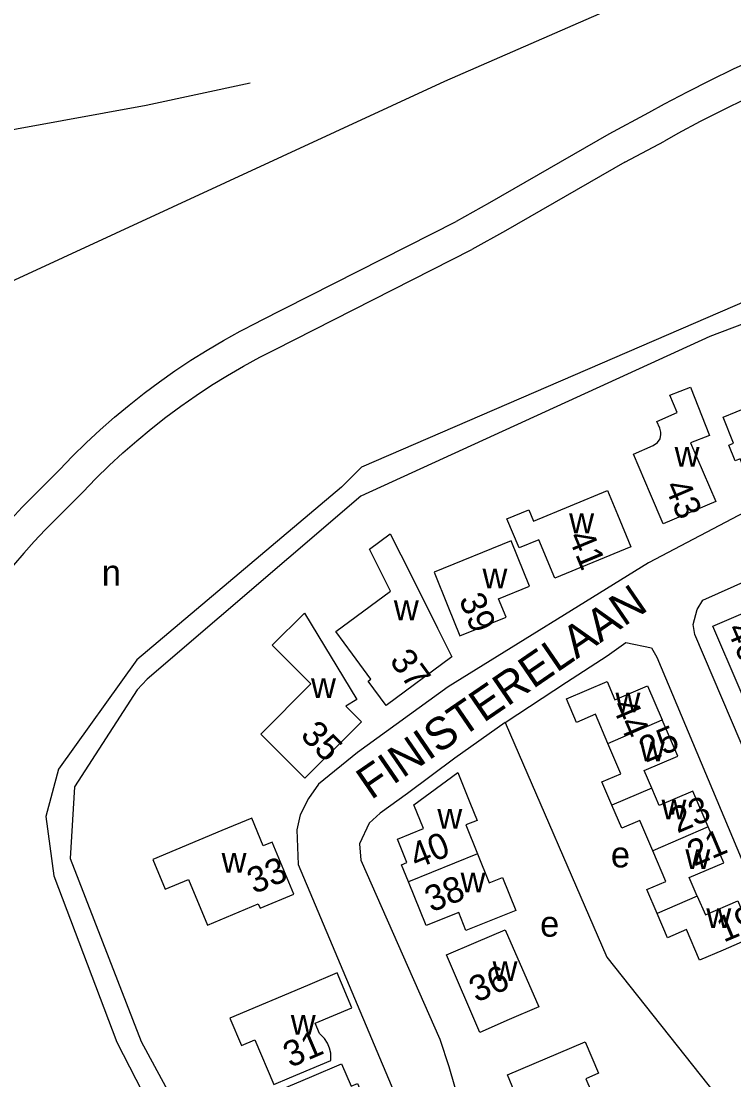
# Model space of a CAD drawing. Extents: x 157768 to 159790, y 387230 to 389604.
# Drawn here: x 158494.9 to 158605.5, y 389072.5 to 389236.8 of the extents above; entities that cross this region are included whole.
import ezdxf

# ---------------------------------------------------------------- set-up
doc = ezdxf.new("R2010")
doc.units = 0
for name, color, linetype in [('BLT_Basislijn', 7, 'Continuous'), ('BLT_Bebouwing', 7, 'Continuous'), ('BLT_Centroide', 7, 'Continuous'), ('BLT_Huisnummer', 7, 'Continuous'), ('BLT_Huisnummer_ tussenligend', 7, 'Continuous'), ('BLT_Onderverdeling_panden', 7, 'Continuous'), ('BLT_Straatnaam', 7, 'Continuous')]:
    doc.layers.add(name, color=color, linetype=linetype)

msp = doc.modelspace()

# ---------------------------------------------------------------- linework, layer by layer
at = {"layer": 'BLT_Basislijn'}
for p, q in [((158592.29, 389222.55), (158586.1, 389219.25)), ((158588.59, 389214.92), (158594.74, 389218.19)), ((158532.02, 389190.28), (158562.46, 389205.73)), ((158534.24, 389185.8), (158564.89, 389201.36)), ((158495.12, 389161.36), (158500.87, 389167.15)), ((158498.66, 389157.84), (158504.5, 389163.72)), ((158509.79, 389078.38), (158523.9, 389050.85))]:
    msp.add_line(p, q, dxfattribs=at)
for points in [[(158651.16, 389267), (158560.63, 389227.45), (158484.33, 389192.23)], [(158620.19, 389235.55), (158616.45, 389234.11), (158612.75, 389232.59), (158609.08, 389230.99), (158605.44, 389229.33), (158601.83, 389227.59), (158598.26, 389225.78), (158594.73, 389223.9), (158592.29, 389222.55)], [(158621.95, 389230.87), (158618.26, 389229.44), (158614.6, 389227.94), (158610.98, 389226.36), (158607.38, 389224.72), (158603.82, 389223), (158600.3, 389221.2), (158596.81, 389219.34), (158594.74, 389218.19)], [(158159.05, 389074.39), (158176.93, 389087.48), (158220.35, 389119.97), (158269.48, 389154.36), (158312.93, 389181.96), (158334.34, 389194.06), (158344.44, 389198.04), (158364.01, 389204.01), (158376.74, 389206.47), (158394.9, 389208.62), (158440.87, 389212.26), (158481.13, 389217.72), (158514.35, 389223.75), (158530.49, 389227.21)], [(158586.1, 389219.25), (158567.61, 389208.61), (158562.46, 389205.73)], [(158588.59, 389214.92), (158570.08, 389204.26), (158564.89, 389201.36)], [(158638.46, 389206.81), (158547.74, 389167.61), (158544.64, 389164.5)], [(158631.85, 389199.23), (158601.81, 389187.85), (158547.63, 389163.08), (158514.51, 389134.71), (158512.92, 389133.02), (158503.21, 389117.99), (158502.57, 389106.88), (158513.55, 389078.5), (158526.29, 389054.94), (158530.22, 389027.48), (158534.69, 389023.17)], [(158500.87, 389167.15), (158502.92, 389169.28), (158505.03, 389171.36), (158507.2, 389173.37), (158509.42, 389175.33), (158511.7, 389177.22), (158514.02, 389179.06), (158516.39, 389180.83), (158518.81, 389182.53), (158521.27, 389184.17), (158523.78, 389185.74), (158526.33, 389187.24), (158528.92, 389188.68), (158531.55, 389190.04), (158532.02, 389190.28)], [(158504.5, 389163.72), (158506.52, 389165.81), (158508.59, 389167.83), (158510.71, 389169.8), (158512.88, 389171.7), (158515.1, 389173.55), (158517.38, 389175.33), (158519.71, 389177.05), (158522.08, 389178.71), (158524.49, 389180.29), (158526.95, 389181.81), (158529.45, 389183.27), (158531.99, 389184.65), (158534.24, 389185.8)], [(158642.21, 389173.46), (158620.23, 389166.55), (158608.23, 389161.14), (158592.3, 389152.76), (158561.19, 389133.52), (158547.15, 389123.34), (158541.1, 389118.4), (158539.51, 389116.18), (158538.23, 389113.63), (158537.74, 389111.33), (158537.91, 389105.95), (158555.4, 389064.46), (158559.68, 389038.08), (158559.64, 389036.09), (158558.78, 389035.34), (158557.73, 389034.76)], [(158544.64, 389164.5), (158512.89, 389137.68), (158500.76, 389120.73), (158498.78, 389113.39), (158500, 389104.19), (158509.79, 389078.38)], [(158609.36, 389118.47), (158599.47, 389141.65), (158599.21, 389143.2), (158599.85, 389145.53), (158600.71, 389146.93), (158631.38, 389160.66), (158643.06, 389163.73), (158643.45, 389163.62), (158648.16, 389157.69), (158654.3, 389147.9)], [(158495.12, 389161.36), (158493.37, 389159.54), (158491.68, 389157.66), (158490.05, 389155.74), (158488.48, 389153.76), (158486.98, 389151.73), (158485.54, 389149.66), (158484.17, 389147.55), (158482.86, 389145.39), (158481.62, 389143.19), (158480.46, 389140.95), (158479.37, 389138.68), (158478.35, 389136.37), (158477.4, 389134.03), (158476.53, 389131.66), (158475.73, 389129.27), (158475.01, 389126.85), (158474.6, 389125.35)], [(158498.66, 389157.84), (158496.97, 389156.07), (158495.34, 389154.26), (158493.77, 389152.39), (158492.26, 389150.47), (158490.81, 389148.5), (158489.43, 389146.49), (158488.12, 389144.43), (158486.87, 389142.33), (158485.69, 389140.19), (158484.59, 389138.01), (158483.55, 389135.8), (158482.59, 389133.55), (158481.7, 389131.28), (158480.89, 389128.98), (158480.15, 389126.65), (158479.49, 389124.3), (158479.44, 389124.11)], [(158570.02, 389127.98), (158579.58, 389134.24), (158585.87, 389138.34), (158588.77, 389140.4), (158592.76, 389139.54), (158593.57, 389138.13), (158611.51, 389095.31), (158612.04, 389093.78)], [(158570.02, 389127.98), (158562.24, 389122.42), (158554.86, 389116.94), (158550.63, 389113.9), (158548.96, 389112.37), (158547.42, 389109.17), (158547.63, 389106.59), (158559.89, 389078.82), (158561.31, 389074.61), (158562.94, 389068.86), (158565.77, 389055.24), (158570.4, 389029.3), (158572.46, 389027.24), (158574.79, 389027.4), (158586.52, 389032.48), (158587.26, 389032.8)], [(158570.02, 389127.98), (158585.83, 389091.57), (158602.65, 389070.31)]]:
    msp.add_lwpolyline(points, dxfattribs=at)
at = {"layer": 'BLT_Bebouwing'}
for points in [[(158598.79, 389180), (158601.72, 389172.52), (158598.81, 389171.38), (158602.7, 389162.25), (158594.55, 389158.78), (158592.59, 389163.38), (158589.93, 389169.62)], [(158589.93, 389169.62), (158592.99, 389170.93), (158593.69, 389171.4), (158594.11, 389172.01), (158594.19, 389172.66), (158594.21, 389173.01), (158594.06, 389173.66), (158593.59, 389174.7), (158596.75, 389176.05), (158595.6, 389178.74), (158598.79, 389180)], [(158618.31, 389169.09), (158615.15, 389167.81), (158613.63, 389171.55), (158612.23, 389170.98), (158613.34, 389168.23), (158607.69, 389165.93), (158606.49, 389168.87), (158605.73, 389168.56), (158604.75, 389170.98), (158605.49, 389171.29), (158603.84, 389175.34), (158613.97, 389179.46), (158614.06, 389179.23)], [(158587.49, 389160.22), (158589.56, 389155.23), (158577.75, 389150.35), (158575.28, 389156.32), (158572.2, 389155.05), (158570.32, 389159.58), (158573.7, 389160.99), (158574.43, 389159.21), (158585.94, 389163.97), (158587.49, 389160.22)], [(158552.26, 389148.34), (158548.99, 389154.87), (158552.22, 389157.24), (158555.49, 389150.71)], [(158571.93, 389153.73), (158570.96, 389156.14), (158559, 389151.3), (158561.13, 389146.04), (158563.01, 389141.4), (158570.17, 389144.29), (158569.01, 389147.16), (158573.81, 389149.1), (158571.93, 389153.73)], [(158555.49, 389150.71), (158559.54, 389142.61)], [(158559.54, 389142.61), (158561.78, 389138.14), (158551.55, 389130.62), (158548.8, 389134.37), (158549.21, 389134.67), (158546.33, 389138.58), (158543.76, 389142.09), (158552.26, 389148.34)], [(158607.53, 389130.59), (158606.33, 389133.39), (158602.27, 389142.92), (158609.14, 389145.85)], [(158545.33, 389130.49), (158547.74, 389128.06), (158538.95, 389119.31), (158535.42, 389122.86), (158532.11, 389126.18), (158539.91, 389133.95), (158533.91, 389139.97), (158538.91, 389144.94), (158547.05, 389131.54), (158545.33, 389130.49)], [(158585.98, 389124.73), (158584.04, 389129.26), (158581.1, 389127.99), (158579.54, 389131.63), (158585.84, 389134.34), (158587.06, 389131.49), (158592.12, 389133.67), (158594.41, 389128.36)], [(158592.77, 389117.8), (158591.61, 389120.51), (158596.82, 389122.75), (158594.41, 389128.36)], [(158586.6, 389115.15), (158585.05, 389118.76), (158588, 389120.03), (158585.98, 389124.73)], [(158555.05, 389103.27), (158553.98, 389105.91), (158554.78, 389106.24), (158553.31, 389109.89), (158557.35, 389111.52), (158555.85, 389115.22), (158562.67, 389120.2), (158564.54, 389115.56), (158565.67, 389112.77), (158563.93, 389112.07), (158565.74, 389107.59)], [(158601.56, 389111.76), (158599.16, 389117.34), (158593.93, 389115.09), (158592.77, 389117.8)], [(158592.93, 389108.05), (158590.92, 389112.74), (158588.15, 389111.55), (158586.6, 389115.15)], [(158532.03, 389099.14), (158537.26, 389101.33), (158533.87, 389109.42), (158532.5, 389108.85), (158530.71, 389113.14), (158526.1, 389111.21), (158515.37, 389106.72), (158517.29, 389102.11), (158520.89, 389103.62), (158523.86, 389096.53), (158531.74, 389099.83), (158532.03, 389099.14)], [(158599.85, 389101.01), (158598.61, 389103.9), (158603.95, 389106.19), (158601.56, 389111.76)], [(158565.74, 389107.59), (158567.55, 389103.11), (158569.61, 389103.94), (158571.68, 389098.81), (158568.6, 389097.57), (158563.96, 389095.69), (158562.83, 389098.48), (158557.8, 389096.45), (158555.05, 389103.27)], [(158593.63, 389098.34), (158592.04, 389102.04), (158594.97, 389103.3), (158592.93, 389108.05)], [(158599.85, 389101.01), (158601.1, 389098.12), (158606.14, 389100.28), (158608.47, 389094.65), (158603.88, 389092.67), (158600.2, 389091.09), (158598.16, 389095.84), (158595.25, 389094.58), (158593.63, 389098.34)], [(158570.68, 389081.87), (158566.09, 389079.87), (158560.92, 389091.93), (158565.52, 389093.89), (158570.06, 389095.82), (158575.27, 389083.87), (158570.68, 389081.87)], [(158539.36, 389087.17), (158527.34, 389082.1), (158529.12, 389077.87), (158531.21, 389078.75), (158534.14, 389071.81), (158536.57, 389072.83), (158543.01, 389075.55), (158542.98, 389076.65), (158542.79, 389077.46), (158542.47, 389078.21), (158542.02, 389078.92), (158541.25, 389079.73), (158540.58, 389081.32), (158546.24, 389083.71), (158543.97, 389089.11), (158539.36, 389087.17)], [(158542.5, 389062.29), (158540.7, 389066.49), (158537.48, 389065.11), (158535, 389070.9), (158540.05, 389073.06), (158544.64, 389075.03), (158546.13, 389071.55), (158547.13, 389071.97), (158549.92, 389065.46)]]:
    msp.add_lwpolyline(points, dxfattribs=at)
msp.add_lwpolyline([(158570.4, 389073.32), (158582.45, 389078.41), (158584.53, 389073.54), (158582.55, 389072.69), (158583.38, 389070.76), (158578.17, 389068.54), (158580.12, 389063.99), (158571.55, 389060.33), (158568.13, 389068.24), (158571.86, 389069.81)], close=True, dxfattribs=at)
at = {"layer": 'BLT_Onderverdeling_panden'}
for p, q in [((158585.98, 389124.73), (158594.41, 389128.36)), ((158592.77, 389117.8), (158586.6, 389115.15)), ((158601.56, 389111.76), (158592.93, 389108.05)), ((158565.74, 389107.59), (158555.05, 389103.27)), ((158599.85, 389101.01), (158593.63, 389098.34))]:
    msp.add_line(p, q, dxfattribs=at)

# ---------------------------------------------------------------- texts
at = {"layer": 'BLT_Centroide'}
for s, p in [('w', (158596.33, 389167.66)), ('w', (158579.97, 389157.34)), ('n', (158507.45, 389149.22)), ('w', (158566.52, 389148.78)), ('w', (158552.77, 389143.83)), ('w', (158539.92, 389131.77)), ('w', (158587.16, 389129.53)), ('w', (158590.94, 389121.94)), ('w', (158594.3, 389112.94)), ('w', (158559.52, 389111.5)), ('e', (158586.44, 389105.49)), ('w', (158598, 389105.22)), ('w', (158526.04, 389104.66)), ('w', (158563.12, 389101.62)), ('w', (158601.25, 389096.06)), ('e', (158575.46, 389094.74)), ('w', (158568.09, 389087.86)), ('w', (158536.78, 389079.52))]:
    msp.add_text(s, height=4, dxfattribs=at).set_placement(p)
at = {"layer": 'BLT_Huisnummer'}
for s, rotation, p in [('43', 293.0888, (158594.7, 389164.66)), ('41', 292.5035, (158579.73, 389156.82)), ('39', 291.9993, (158562.81, 389147.11)), ('46', 293.0932, (158604.35, 389142.53)), ('37', 306.3128, (158551.98, 389137.53)), ('44', 293.2577, (158586.52, 389130.65)), ('35', 314.8542, (158538.11, 389125.84)), ('25', 22.8346, (158591.87, 389121.7)), ('40', 21.9934, (158556.26, 389105.21)), ('33', 22.7199, (158531.07, 389101.31)), ('38', 21.995, (158558.59, 389098.47)), ('19', 22.8346, (158603.94, 389093.8)), ('36', 23.5612, (158565.56, 389084.47)), ('31', 23.1833, (158536.69, 389074.35))]:
    msp.add_text(s, height=4, rotation=rotation, dxfattribs=at).set_placement(p)
at = {"layer": 'BLT_Huisnummer_ tussenligend'}
for s, p in [('23', (158596.76, 389110.73)), ('21', (158599.35, 389105.6))]:
    msp.add_text(s, height=4, rotation=22.8346, dxfattribs=at).set_placement(p)
at = {"layer": 'BLT_Straatnaam'}
msp.add_text('FINISTERELAAN', height=5, rotation=34.4326, dxfattribs=at).set_placement((158549.23, 389115.89))

doc.saveas('drawing.dxf')
